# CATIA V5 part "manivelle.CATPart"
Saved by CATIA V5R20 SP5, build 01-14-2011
Part number: manivelle
Publications: "Longueur_manivelle"
Bounding box of the stored display mesh (mm): x 0 to 40, y -20 to 10, z -15 to 50
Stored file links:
  M:\EU_thinkMotion\IAO_2010\iao\IAO_MMS_Groupe2\IAO_MMS_Groupe2\rwatrin\rwatrin\manivelle.CATPart
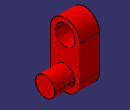
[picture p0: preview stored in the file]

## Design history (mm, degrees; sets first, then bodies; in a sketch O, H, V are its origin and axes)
Parameters
  Longueur_manivelle = 132.852 mm
Body1 (main body)
  Sketch1 on yz-plane, origin (0, 0, 0), H (0, 1, 0), V (0, 0, 1)
    point P1 (-20, 0)
    line L1 (-20, 0) -> (-20, 35)
    arc A1 centre (-5, 35) radius 15 from (-20, 35) to (10, 35) cw
    point P3 (-5, 35)
    line L2 (10, 35) -> (10, 0)
    point P5 (10, 0)
    arc A2 centre (-5, 0) radius 15 from (10, 0) to (-20, 0) cw
    point P6 (-5, 0)
    circle A3 centre (-5, 35) radius 10
    distance L2 L1 = 30
    radius A3 = 10
    distance P6 P3 = 35
    coincidence: P1 H, P5 H
    vertical: L1 V
    tangency: A1 L1, L2 A1, A2 L1, A2 L2
  Pad1: profile Sketch1, direction (1, 0, 0), length 20
  Sketch2 on end face of Pad1, origin (20, 0, 0), H (0, 1, 0), V (0, 0, 1)
    circle A1 centre (-5, 0) radius 10
    point P1 (-5, 0)
    reference projected line E1 (10, 0) -> (10, 35) from edge [face of Pad1 from Sketch1.L2 | end face of Pad1]
    reference projected circle E2 centre (-5, 35) radius 10 from edge [end face of Pad1 | face of Pad1 from Sketch1.A3]
    radius A1 = 10
    distance A1 E1 = 5
    distance E2 P1 = 25
  Pad2: profile Sketch2, direction (1, 0, 0), length 20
